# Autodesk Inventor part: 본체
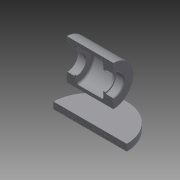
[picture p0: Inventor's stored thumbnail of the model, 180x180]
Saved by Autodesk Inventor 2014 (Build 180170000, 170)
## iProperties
Created: 2018-12
Part Number: 본체
Material: Generic
Document SubType Name: Modeling
Designer: kh
Density: 1 g/cm^3
Appearance: Default
Author: kh
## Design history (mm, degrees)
sketch "Sketch1"
  geometry: C1 r 55 at (0, 0); 1 further point
  constraints: 1 centre point, 1 coincident
  dimensions: "d0" = 110 diameter of C1
extrude "Extrusion1" new body sketch "Sketch1" distance "d1" = 10; taper "d2" = 0 deg
sketch "Sketch2"
  geometry: L1 (55, 10)-(-55, 10) reference; L2 (-55, 0)-(55, 0) reference; L3 (35, 75)-(-35, 75); L4 (0, 0)-(0, 161.795); L5 (0, 0)-(0, 75); L6 (35, 75)-(35, 105); L7 (35, 105)-(-35, 105); L8 (-35, 105)-(-35, 75)
  constraints: 12 end point, 3 parallel, 2 perpendicular, 1 midpoint, 1 point on line
  dimensions: "d3" = 70 distance of L3.start L3.end; "d4" = 75 distance of L5.end L4.start; "d5" = 60 diameter of L7 L3
revolve "Revolution1" sketch "Sketch2" stored, may be unused: angle "d6" = 90 deg
sketch "Sketch3"
  geometry: L1 (35, 45)-(35, 105) reference; L2 (-35, 45)-(-35, 105) reference; L3 (35, 75)-(-35, 75); L4 (35, 91)-(23, 91); L5 (23, 91)-(23, 89); L6 (23, 89)-(20, 89); L7 (20, 89)-(20, 100); L8 (20, 100)-(-20, 100); L9 (-20, 100)-(-20, 89); L10 (-20, 89)-(-23, 89); L11 (-23, 89)-(-23, 91); L12 (-23, 91)-(-35, 91); L13 (0, 75)-(0, 112.28); L14 (35, 91)-(35, 75); L15 (-35, 91)-(-35, 75); 2 further points
  constraints: 26 end point, 7 parallel, 4 midpoint, 4 perpendicular, 3 point on line, 1 collinear
  dimensions: "d7" = 32 diameter of L4 L3; "d8" = 28 diameter of L6 L3; "d9" = 50 diameter of L8 L3; "d10" = 28 diameter of L10 L3; "d11" = 32 diameter of L12 L3; "d12" = 40 distance of L8.end L7.end; "d13" = 3 horizontal distance of L7.end L4.end; "d14" = 3 distance of L10.end L9.end
revolve "Revolution2" sketch "Sketch3" stored, may be unused: angle "d15" = 90 deg
chamfer "Chamfer1" distance "d16" = 1; stored, may be unused: second distance "d17" = 2, angle "d18" = 45 deg
fillet "Fillet1" dims "d19" = 3
fillet "Fillet2" dims "d20" = 0.3
body "Solid1"
node "Projected Loop1"
node "Projected Loop2"
